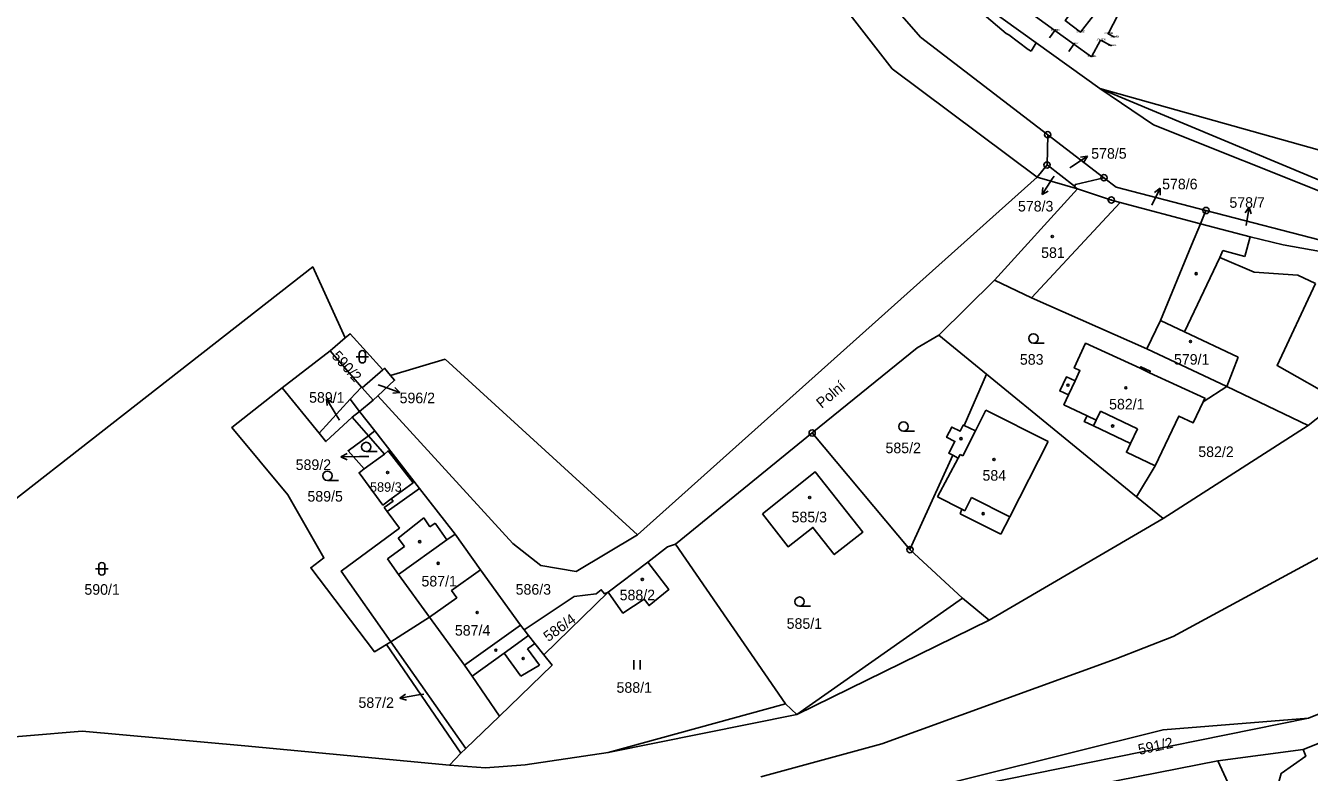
# Model space of a CAD drawing. Extents: x -776701 to -776081, y -974398 to -973771.
# Drawn here: x -776586.6 to -776380.3, y -974307.7 to -974187.7 of the extents above; entities that cross this region are included whole.
import ezdxf

# ---------------------------------------------------------------- set-up
doc = ezdxf.new("R2010")
doc.units = 0
for name, color, linetype in [('1 Body-bod', 7, 'Continuous'), ('10 Silnice-chodniky', 7, 'Continuous'), ('2 Body-cislo', 7, 'Continuous'), ('3 Body-vyska', 7, 'Continuous'), ('5 Budovy', 7, 'Continuous'), ('7 Ploty', 7, 'Continuous'), ('Hranice parcel', 7, 'Continuous'), ('Parcelní čísla', 7, 'Continuous'), ('Pop  PČ popisy', 7, 'Continuous'), ('Poz předměty', 7, 'Continuous'), ('Vnitřní kresba', 7, 'Continuous'), ('Značky bodu BP', 7, 'Continuous'), ('Značky budov', 7, 'Continuous'), ('Značky kultur', 7, 'Continuous')]:
    doc.layers.add(name, color=color, linetype=linetype)

msp = doc.modelspace()

# ---------------------------------------------------------------- linework, layer by layer
at = {"layer": '1 Body-bod'}
for p, q in [((-776421.23, -974188.49), (-776421.23, -974188.49)), ((-776417.11, -974188.76), (-776417.11, -974188.76)), ((-776412.65, -974189.02), (-776412.65, -974189.02)), ((-776411.65, -974189.55), (-776411.65, -974189.55)), ((-776418.2, -974190.66), (-776418.2, -974190.66)), ((-776413.87, -974190.05), (-776413.87, -974190.05)), ((-776412.11, -974190.94), (-776412.11, -974190.94)), ((-776415.33, -974192.73), (-776415.33, -974192.73))]:
    msp.add_line(p, q, dxfattribs=at)
at = {"layer": '10 Silnice-chodniky'}
msp.add_lwpolyline([(-776408.59, -974183.13), (-776409.43, -974182.72), (-776412.65, -974189.02), (-776411.65, -974189.55)], dxfattribs=at)
at = {"layer": '5 Budovy'}
msp.add_lwpolyline([(-776412.11, -974190.94), (-776413.87, -974190.05), (-776415.33, -974192.73)], dxfattribs=at)
at = {"layer": '7 Ploty'}
for p, q in [((-776421.23, -974188.49), (-776422.08, -974189.63)), ((-776418.2, -974190.66), (-776419, -974191.83))]:
    msp.add_line(p, q, dxfattribs=at)
for points in [[(-776415.33, -974192.73), (-776418.2, -974190.66), (-776421.23, -974188.49), (-776424.36, -974186.24), (-776427.39, -974184), (-776430.07, -974181.99), (-776432.38, -974179.43), (-776434.94, -974176.63), (-776434.87, -974176.53), (-776437.47, -974173.79), (-776440.34, -974170.82), (-776442.68, -974168.36), (-776445.15, -974165.67), (-776446.94, -974163.01), (-776451.45, -974156.97), (-776456.49, -974149.91), (-776458.27, -974147.5), (-776460.71, -974144.17), (-776461.87, -974145.07)], [(-776410.02, -974178.63), (-776411.75, -974182.02), (-776414.07, -974185.17), (-776414.88, -974186.15), (-776415.02, -974186.06), (-776417.11, -974188.76), (-776419.58, -974186.86), (-776418.35, -974185.27), (-776418.07, -974185.5), (-776417.25, -974184.38), (-776417.17, -974184.42), (-776416.48, -974183.46), (-776415.65, -974182.42), (-776415.01, -974181.59), (-776414.32, -974180.57), (-776411.96, -974176.29), (-776407.95, -974168.57), (-776405.03, -974163.01), (-776402.53, -974158.19), (-776400.94, -974155.22), (-776397.47, -974148.58), (-776394.68, -974143.21), (-776392.14, -974144.47)]]:
    msp.add_lwpolyline(points, dxfattribs=at)
at = {"layer": 'Hranice parcel'}
for p, q in [((-776424.22, -974190.48), (-776425.04, -974191.8)), ((-776424.22, -974190.48), (-776414.02, -974197.79)), ((-776405.4, -974203.66), (-776414.02, -974197.79)), ((-776414.02, -974197.79), (-776375.42, -974208.63)), ((-776422.47, -974210.08), (-776422.37, -974205.22)), ((-776422.37, -974205.22), (-776413.34, -974212.14)), ((-776424.09, -974212.03), (-776422.47, -974210.08)), ((-776418.08, -974213.51), (-776422.47, -974210.08)), ((-776424.09, -974212.03), (-776417.57, -974213.91)), ((-776417.57, -974213.91), (-776430.93, -974228.6)), ((-776417.57, -974213.91), (-776418.08, -974213.51)), ((-776397.85, -974219.54), (-776396.96, -974217.4)), ((-776430.93, -974228.6), (-776439.87, -974237.43)), ((-776439.87, -974237.43), (-776432.18, -974243.72)), ((-776406.44, -974239.65), (-776393.62, -974245.71)), ((-776532.52, -974245.88), (-776529.21, -974243.01)), ((-776432.18, -974243.72), (-776435.78, -974251.95)), ((-776432.18, -974243.72), (-776408.09, -974263.43)), ((-776534.44, -974247.75), (-776532.6, -974245.78)), ((-776532.6, -974245.78), (-776532.52, -974245.88)), ((-776393.62, -974245.71), (-776397.41, -974248.18)), ((-776393.62, -974245.71), (-776380.54, -974251.96)), ((-776534.44, -974247.75), (-776539.44, -974253.17)), ((-776532.93, -974249.69), (-776534.44, -974247.75)), ((-776375.51, -974247.99), (-776380.54, -974251.96)), ((-776530.48, -974252.84), (-776532.93, -974249.69)), ((-776531.5, -974253.6), (-776530.48, -974252.84)), ((-776523.3, -974262.08), (-776530.48, -974252.84)), ((-776460.21, -974253.15), (-776482.16, -974271.01)), ((-776444.5, -974271.91), (-776460.21, -974253.15)), ((-776380.54, -974251.96), (-776403.84, -974266.91)), ((-776437.64, -974256.73), (-776444.5, -974271.91)), ((-776405.12, -974258.44), (-776408.09, -974263.43)), ((-776523.3, -974262.08), (-776528.47, -974265.8)), ((-776408.09, -974263.43), (-776403.84, -974266.91)), ((-776403.84, -974266.91), (-776431.78, -974283.23)), ((-776483.46, -974271.48), (-776486.63, -974273.9)), ((-776482.16, -974271.01), (-776483.46, -974271.48)), ((-776486.63, -974273.9), (-776493, -974278.76)), ((-776506.48, -974284.82), (-776498.47, -974279.44)), ((-776493, -974278.76), (-776503.32, -974288.82)), ((-776431.78, -974283.23), (-776462.69, -974298.42)), ((-776505.76, -974285.73), (-776506.48, -974284.82)), ((-776527.9, -974286.72), (-776528.58, -974287.14)), ((-776528.58, -974287.14), (-776516.67, -974304.61)), ((-776515.87, -974303.85), (-776527.9, -974286.72)), ((-776366.62, -974298.19), (-776381.33, -974304.06)), ((-776380.5, -974299.02), (-776464.24, -974315.93)), ((-776518.5, -974306.54), (-776516.67, -974304.61)), ((-776516.67, -974304.61), (-776515.87, -974303.85)), ((-776395.04, -974305.86), (-776381.33, -974304.06)), ((-776395.04, -974305.86), (-776417.64, -974310.29)), ((-776393.45, -974309.32), (-776395.04, -974305.86))]:
    msp.add_line(p, q, dxfattribs=at)
for points in [[(-776422.37, -974205.22), (-776442.82, -974189.54), (-776456.08, -974174.28), (-776488.55, -974129.25), (-776501.63, -974111.28)], [(-776502.39, -974119.39), (-776493.32, -974132.93), (-776460.49, -974177.7), (-776447.38, -974194.61), (-776424.09, -974212.03)], [(-776425.04, -974191.8), (-776425.52, -974191.53), (-776428.6, -974189.19), (-776429.03, -974188.93), (-776432.88, -974185.68), (-776433.29, -974185.39), (-776435.41, -974183.26), (-776435.78, -974182.9), (-776438.08, -974180.06), (-776438.65, -974179.7), (-776443.59, -974174.45), (-776443.94, -974174.06), (-776448.63, -974169.08), (-776448.94, -974168.67), (-776452.87, -974162.91), (-776453.18, -974162.44), (-776459.11, -974154.55), (-776459.39, -974154.1), (-776461.5, -974151.3), (-776461.83, -974150.84), (-776461.03, -974150.2)], [(-776441.53, -974172.59), (-776432.39, -974184.63), (-776424.22, -974190.48)], [(-776372.39, -974215.17), (-776376.43, -974215.22), (-776405.4, -974203.66)], [(-776530.01, -974247.21), (-776508.29, -974270.92), (-776503.78, -974274.48), (-776498.15, -974275.4), (-776488.25, -974269.53), (-776424.09, -974212.03)], [(-776418.08, -974213.51), (-776417.92, -974213.2), (-776413.34, -974212.14)], [(-776413.34, -974212.14), (-776411.37, -974213.65), (-776396.96, -974217.4)], [(-776397.85, -974219.54), (-776410.75, -974216.12), (-776412.14, -974215.72), (-776417.57, -974213.91)], [(-776396.96, -974217.4), (-776377.08, -974222.57), (-776374.7, -974223.37)], [(-776397.85, -974219.54), (-776399.26, -974222.98), (-776404.25, -974235.1), (-776406.44, -974239.65)], [(-776377.04, -974224.25), (-776384.52, -974222.93), (-776389.85, -974221.65), (-776397.85, -974219.54)], [(-776535.24, -974237.89), (-776540.45, -974226.46), (-776624.42, -974292.05)], [(-776430.93, -974228.6), (-776424.97, -974231.42), (-776406.44, -974239.65)], [(-776375.51, -974247.99), (-776385.52, -974242.34), (-776379.34, -974229.15)], [(-776532.6, -974245.78), (-776537.64, -974239.96), (-776535.24, -974237.89)], [(-776529.21, -974243.01), (-776534.45, -974237.21), (-776535.24, -974237.89)], [(-776439.87, -974237.43), (-776443.37, -974239.45), (-776460.21, -974253.15)], [(-776397.41, -974248.18), (-776397.12, -974247.56), (-776406, -974243.47), (-776405.89, -974243.22), (-776407.43, -974242.51), (-776407.54, -974242.75), (-776416.28, -974238.73), (-776418.12, -974242.71), (-776417.19, -974243.14), (-776417.97, -974244.8), (-776419.38, -974244.14), (-776420.43, -974246.39), (-776419.05, -974247.04), (-776419.78, -974248.62), (-776416.06, -974250.39), (-776416.51, -974251.32), (-776415.03, -974252.03), (-776409.06, -974254.87), (-776409.72, -974256.26), (-776405.12, -974258.44)], [(-776529.21, -974243.01), (-776528.91, -974242.75), (-776527.96, -974243.9), (-776527.3, -974244.69), (-776530.01, -974247.21)], [(-776539.44, -974253.17), (-776545.36, -974245.91), (-776553.45, -974252.29), (-776544.44, -974263.09), (-776538.65, -974273.25), (-776540.78, -974274.81), (-776530.52, -974288.35), (-776528.58, -974287.14)], [(-776532.52, -974245.88), (-776530.72, -974247.87), (-776530.01, -974247.21)], [(-776405.12, -974258.44), (-776401.32, -974250.45), (-776399.02, -974251.55), (-776397.41, -974248.18)], [(-776539.44, -974253.17), (-776538.32, -974254.54), (-776534.1, -974250.64), (-776531.5, -974253.6)], [(-776435.78, -974251.95), (-776435.93, -974251.88), (-776436.45, -974252.88), (-776437.78, -974252.2), (-776438.62, -974253.84), (-776437.29, -974254.52), (-776438.26, -974256.41), (-776437.64, -974256.73)], [(-776531.5, -974253.6), (-776534.78, -974256.03), (-776532.19, -974258.93)], [(-776532.19, -974258.93), (-776528.92, -974256.54), (-776528.33, -974256.02), (-776524.32, -974261.16), (-776527.85, -974263.77)], [(-776532.19, -974258.93), (-776533, -974259.54), (-776529.16, -974264.74), (-776527.85, -974263.77)], [(-776468.21, -974266.18), (-776459.73, -974259.41), (-776452.1, -974269.12), (-776456.67, -974272.7), (-776460.08, -974268.34), (-776464.07, -974271.46), (-776468.21, -974266.18)], [(-776527.85, -974263.77), (-776527.55, -974264.1), (-776528.95, -974265.14), (-776528.47, -974265.8)], [(-776513.48, -974275.16), (-776517.59, -974269.43), (-776523.3, -974262.08)], [(-776528.47, -974265.8), (-776526.51, -974268.44), (-776535.87, -974275.37), (-776527.9, -974286.72)], [(-776380.5, -974299.02), (-776354.39, -974288.37), (-776324.88, -974267.68)], [(-776482.16, -974271.01), (-776464.48, -974296.69), (-776462.69, -974298.42)], [(-776444.5, -974271.91), (-776436.05, -974279.71), (-776431.78, -974283.23)], [(-776486.63, -974273.9), (-776483.24, -974278.33), (-776486.41, -974280.89), (-776487.19, -974279.85), (-776490.62, -974282.12), (-776493, -974278.76)], [(-776527.9, -974286.72), (-776521.69, -974282.79), (-776517.3, -974279.65), (-776518.13, -974278.48), (-776513.48, -974275.16)], [(-776506.48, -974284.82), (-776507.09, -974284.04), (-776513.48, -974275.16)], [(-776498.47, -974279.44), (-776494.93, -974279.02), (-776494.09, -974278.37), (-776493.6, -974278.99), (-776493, -974278.76)], [(-776503.32, -974288.82), (-776504.76, -974286.99), (-776505.76, -974285.73)], [(-776515.87, -974303.85), (-776510.45, -974298.7), (-776502, -974290.5), (-776503.32, -974288.82)], [(-776462.69, -974298.42), (-776493, -974304.5), (-776506.3, -974306.5), (-776512.68, -974307), (-776518.5, -974306.54)], [(-776464.24, -974315.93), (-776403.84, -974300.87), (-776380.5, -974299.02)], [(-776518.5, -974306.54), (-776551.36, -974303.43), (-776577.49, -974301.09), (-776595.43, -974302.58), (-776588.8, -974320), (-776592.85, -974321.75)], [(-776381.33, -974304.06), (-776380.93, -974305.13), (-776384.89, -974307.87), (-776385.42, -974309.83), (-776385.09, -974312.64), (-776383.44, -974315.62), (-776375.79, -974324.92)]]:
    msp.add_lwpolyline(points, dxfattribs=at)
at = {"layer": 'Pop  PČ popisy'}
for p, q in [((-776418.49, -974210.34), (-776416, -974208.66)), ((-776416, -974208.66), (-776417.11, -974208.81)), ((-776416, -974208.66), (-776416.55, -974209.64)), ((-776421.35, -974211.87), (-776421.64, -974212.33)), ((-776418.8, -974210.54), (-776418.49, -974210.34)), ((-776421.64, -974212.33), (-776423.27, -974214.85)), ((-776423.27, -974214.85), (-776423.15, -974213.73)), ((-776423.27, -974214.85), (-776422.31, -974214.28)), ((-776405.63, -974216.53), (-776404.31, -974213.83)), ((-776404.31, -974213.83), (-776405.2, -974214.51)), ((-776404.31, -974213.83), (-776404.3, -974214.95)), ((-776390.01, -974216.86), (-776390.66, -974217.77)), ((-776390.48, -974219.82), (-776390.01, -974216.86)), ((-776390.01, -974216.86), (-776389.67, -974217.92)), ((-776529.95, -974245.43), (-776529.3, -974245.66)), ((-776529.3, -974245.66), (-776526.46, -974246.64)), ((-776526.46, -974246.64), (-776527.57, -974246.78)), ((-776526.46, -974246.64), (-776527.25, -974245.84)), ((-776536.68, -974250.22), (-776538.23, -974247.65)), ((-776538.23, -974247.65), (-776537.28, -974248.25)), ((-776538.23, -974247.65), (-776538.14, -974248.76)), ((-776536.17, -974251.08), (-776536.68, -974250.22)), ((-776535.93, -974256.99), (-776534.94, -974256.47)), ((-776532.93, -974256.94), (-776535.93, -974256.99)), ((-776535.93, -974256.99), (-776534.92, -974257.48)), ((-776531.43, -974256.92), (-776532.93, -974256.94)), ((-776526.44, -974295.79), (-776525.54, -974295.12)), ((-776523.48, -974295.27), (-776526.44, -974295.79)), ((-776526.44, -974295.79), (-776525.36, -974296.11)), ((-776522.6, -974295.12), (-776523.48, -974295.27))]:
    msp.add_line(p, q, dxfattribs=at)
at = {"layer": 'Poz předměty'}
for p, q in [((-776402.2, -974285.89), (-776375.83, -974271.58)), ((-776411.53, -974289.53), (-776402.2, -974285.89)), ((-776449.01, -974303.15), (-776411.53, -974289.53)), ((-776468.46, -974308.41), (-776449.01, -974303.15))]:
    msp.add_line(p, q, dxfattribs=at)
at = {"layer": 'Vnitřní kresba'}
for p, q in [((-776414.02, -974197.79), (-776372.39, -974215.17)), ((-776424.97, -974231.42), (-776410.75, -974216.12)), ((-776389.85, -974221.65), (-776390.73, -974224.8)), ((-776394.22, -974223.82), (-776394.74, -974224.93)), ((-776390.73, -974224.8), (-776394.22, -974223.82)), ((-776394.74, -974224.93), (-776400.42, -974236.93)), ((-776394.74, -974224.93), (-776389.22, -974227.33)), ((-776389.22, -974227.33), (-776382.19, -974227.77)), ((-776382.19, -974227.77), (-776379.34, -974229.15)), ((-776400.42, -974236.93), (-776404.25, -974235.1)), ((-776400.42, -974236.93), (-776391.77, -974240.97)), ((-776545.36, -974245.91), (-776537.64, -974239.96)), ((-776391.77, -974240.97), (-776393.62, -974245.71)), ((-776527.96, -974243.9), (-776519.17, -974241.29)), ((-776488.25, -974269.53), (-776519.17, -974241.29)), ((-776407.54, -974242.75), (-776406, -974243.47)), ((-776419.05, -974247.04), (-776417.97, -974244.8)), ((-776532.93, -974249.69), (-776530.72, -974247.87)), ((-776532.93, -974249.69), (-776534.1, -974250.64)), ((-776432.3, -974249.51), (-776433.97, -974252.81)), ((-776422.32, -974254.55), (-776432.3, -974249.51)), ((-776414.58, -974251.09), (-776416.06, -974250.39)), ((-776414.58, -974251.09), (-776415.03, -974252.03)), ((-776413.9, -974249.65), (-776414.58, -974251.09)), ((-776407.93, -974252.47), (-776413.9, -974249.65)), ((-776436.03, -974256.85), (-776433.97, -974252.81)), ((-776433.97, -974252.81), (-776435.78, -974251.95)), ((-776407.93, -974252.47), (-776409.06, -974254.87)), ((-776528.92, -974256.54), (-776531.5, -974253.6)), ((-776422.32, -974254.55), (-776428.45, -974266.64)), ((-776440.09, -974263.43), (-776436.74, -974257.2)), ((-776437.64, -974256.73), (-776436.74, -974257.2)), ((-776436.74, -974257.2), (-776436.44, -974256.63)), ((-776436.44, -974256.63), (-776436.03, -974256.85)), ((-776436.15, -974265.43), (-776440.09, -974263.43)), ((-776434.59, -974263.53), (-776435.67, -974265.67)), ((-776434.59, -974263.53), (-776428.45, -974266.64)), ((-776436.15, -974265.43), (-776436.44, -974266.14)), ((-776435.67, -974265.67), (-776436.15, -974265.43)), ((-776526.72, -974270.08), (-776522.58, -974266.8)), ((-776522.58, -974266.8), (-776521.63, -974268.26)), ((-776521.63, -974268.26), (-776520.8, -974267.64)), ((-776520.8, -974267.64), (-776518.89, -974270.35)), ((-776436.44, -974266.14), (-776429.91, -974269.45)), ((-776429.91, -974269.45), (-776428.45, -974266.64)), ((-776517.59, -974269.43), (-776518.89, -974270.35)), ((-776528.45, -974273.38), (-776525.69, -974271.39)), ((-776526.72, -974270.08), (-776525.69, -974271.39)), ((-776518.89, -974270.35), (-776526.69, -974275.93)), ((-776526.69, -974275.93), (-776528.45, -974273.38)), ((-776526.69, -974275.93), (-776521.69, -974282.79)), ((-776462.69, -974298.42), (-776436.05, -974279.71)), ((-776521.69, -974282.79), (-776516.07, -974290.5)), ((-776516.07, -974290.5), (-776507.09, -974284.04)), ((-776505.76, -974285.73), (-776509.69, -974288.56)), ((-776509.69, -974288.56), (-776514.86, -974292.27)), ((-776509.69, -974288.56), (-776507.03, -974292.26)), ((-776505.92, -974287.83), (-776504.76, -974286.99)), ((-776504.01, -974290.49), (-776505.92, -974287.83)), ((-776516.07, -974290.5), (-776514.86, -974292.27)), ((-776507.03, -974292.26), (-776504.01, -974290.49)), ((-776514.86, -974292.27), (-776510.45, -974298.7)), ((-776493, -974304.5), (-776464.48, -974296.69))]:
    msp.add_line(p, q, dxfattribs=at)
at = {"layer": 'Značky bodu BP'}
for centre, radius in [((-776422.37, -974205.22), 0.5), ((-776422.37, -974205.22), 0.0303), ((-776422.47, -974210.08), 0.5), ((-776422.47, -974210.08), 0.0303), ((-776413.34, -974212.14), 0.5), ((-776413.34, -974212.14), 0.0303), ((-776412.14, -974215.72), 0.5), ((-776412.14, -974215.72), 0.0303), ((-776396.96, -974217.4), 0.5), ((-776396.96, -974217.4), 0.0303), ((-776460.21, -974253.15), 0.5), ((-776460.21, -974253.15), 0.0303), ((-776444.5, -974271.91), 0.5), ((-776444.5, -974271.91), 0.0303)]:
    msp.add_circle(centre, radius, dxfattribs=at)
at = {"layer": 'Značky budov'}
for centre in [(-776421.64, -974221.59), (-776398.53, -974227.56), (-776399.43, -974238.45), (-776419.12, -974245.48), (-776409.83, -974245.9), (-776411.94, -974252.05), (-776436.3, -974254.07), (-776431, -974257.43), (-776528.42, -974259.52), (-776460.61, -974263.54), (-776432.74, -974266.12), (-776523.26, -974270.63), (-776520.3, -974274.12), (-776487.5, -974276.7), (-776514.03, -974282.01), (-776511.03, -974288.06), (-776506.65, -974289.41)]:
    msp.add_circle(centre, 0.175, dxfattribs=at)
at = {"layer": 'Značky kultur'}
for p, q in [((-776424.67, -974238.71), (-776422.92, -974238.71)), ((-776533.49, -974240.91), (-776531.49, -974240.91)), ((-776532.99, -974240.41), (-776532.99, -974241.41)), ((-776531.99, -974241.41), (-776531.99, -974240.41)), ((-776445.54, -974252.89), (-776443.79, -974252.89)), ((-776531.85, -974256.16), (-776530.1, -974256.16)), ((-776538.08, -974260.79), (-776536.33, -974260.79)), ((-776575.33, -974275), (-776573.33, -974275)), ((-776574.83, -974274.5), (-776574.83, -974275.5)), ((-776573.83, -974275.5), (-776573.83, -974274.5)), ((-776462.23, -974281.02), (-776460.48, -974281.02)), ((-776488.85, -974291.19), (-776488.85, -974289.69)), ((-776487.85, -974291.19), (-776487.85, -974289.69))]:
    msp.add_line(p, q, dxfattribs=at)
for centre in [(-776424.67, -974237.96), (-776445.54, -974252.14), (-776531.85, -974255.41), (-776538.08, -974260.04), (-776462.23, -974280.27)]:
    msp.add_circle(centre, 0.75, dxfattribs=at)
for centre, start, end in [((-776532.49, -974240.41), 0, 180), ((-776532.49, -974241.41), 180, 359.9879), ((-776574.33, -974274.5), 0, 180), ((-776574.33, -974275.5), 180, 359.9879)]:
    msp.add_arc(centre, 0.5, start, end, dxfattribs=at)

# ---------------------------------------------------------------- texts
at = {"layer": '2 Body-cislo'}
for s, p in [('2018', (-776421.23, -974188.49)), ('2037', (-776417.11, -974188.76)), ('2012', (-776412.65, -974189.02)), ('2013', (-776411.65, -974189.55)), ('2017', (-776418.2, -974190.66)), ('2015', (-776413.87, -974190.05)), ('2014', (-776412.11, -974190.94)), ('2016', (-776415.33, -974192.73))]:
    msp.add_text(s, height=0.25, dxfattribs=at).set_placement(p)
at = {"layer": '3 Body-vyska'}
for s, p in [('274.930', (-776421.88, -974188.49)), ('274.850', (-776417.75, -974188.76)), ('274.780', (-776413.28, -974189.02)), ('274.780', (-776412.28, -974189.55)), ('274.920', (-776418.84, -974190.66)), ('274.930', (-776414.52, -974190.05)), ('274.810', (-776412.7, -974190.94)), ('274.940', (-776415.96, -974192.73))]:
    msp.add_text(s, height=0.25, dxfattribs=at).set_placement(p)
at = {"layer": 'Parcelní čísla'}
for s, height, p in [('578/5', 1.7, (-776415.38, -974209.08)), ('578/6', 1.7, (-776403.99, -974214)), ('578/3', 1.7, (-776427.15, -974217.56)), ('578/7', 1.7, (-776393.18, -974216.97)), ('581', 1.7, (-776423.43, -974225.03)), ('583', 1.7, (-776426.84, -974242.19)), ('579/1', 1.7, (-776402.09, -974242.18)), ('589/1', 1.7, (-776541.03, -974248.3)), ('596/2', 1.7, (-776526.49, -974248.38)), ('582/1', 1.7, (-776412.51, -974249.38)), ('585/2', 1.7, (-776448.43, -974256.41)), ('582/2', 1.7, (-776398.18, -974257.03)), ('589/2', 1.7, (-776543.19, -974259.11)), ('584', 1.7, (-776432.85, -974260.83)), ('589/3', 1.524, (-776531.25, -974262.61)), ('589/5', 1.7, (-776541.3, -974264.19)), ('585/3', 1.7, (-776463.52, -974267.53)), ('587/1', 1.7, (-776522.98, -974277.83)), ('590/1', 1.7, (-776577.13, -974279.16)), ('586/3', 1.7, (-776507.85, -974279.15)), ('588/2', 1.7, (-776491.14, -974280.05)), ('587/4', 1.7, (-776517.61, -974285.73)), ('585/1', 1.7, (-776464.31, -974284.64)), ('588/1', 1.7, (-776491.64, -974294.92)), ('587/2', 1.7, (-776533.1, -974297.35))]:
    msp.add_text(s, height=height, dxfattribs=at).set_placement(p)
for s, rotation, p in [('590/2', 312, (-776537.51, -974240.88)), ('586/4', 36, (-776502.61, -974286.8)), ('591/2', 12, (-776407.66, -974304.9))]:
    msp.add_text(s, height=1.7, rotation=rotation, dxfattribs=at).set_placement(p)
at = {"layer": 'Pop  PČ popisy'}
msp.add_text('Polní', height=1.7, rotation=40, dxfattribs=at).set_placement((-776458.68, -974249.28))

doc.saveas('drawing.dxf')
